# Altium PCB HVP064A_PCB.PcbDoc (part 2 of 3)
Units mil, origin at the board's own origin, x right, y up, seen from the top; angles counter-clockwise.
Board outline 5750 x 4500 mil, 2 copper layers (Top Layer, Bottom Layer), stack 62 mil thick; 174 components, 71 nets, 376 pads, 361 vias.
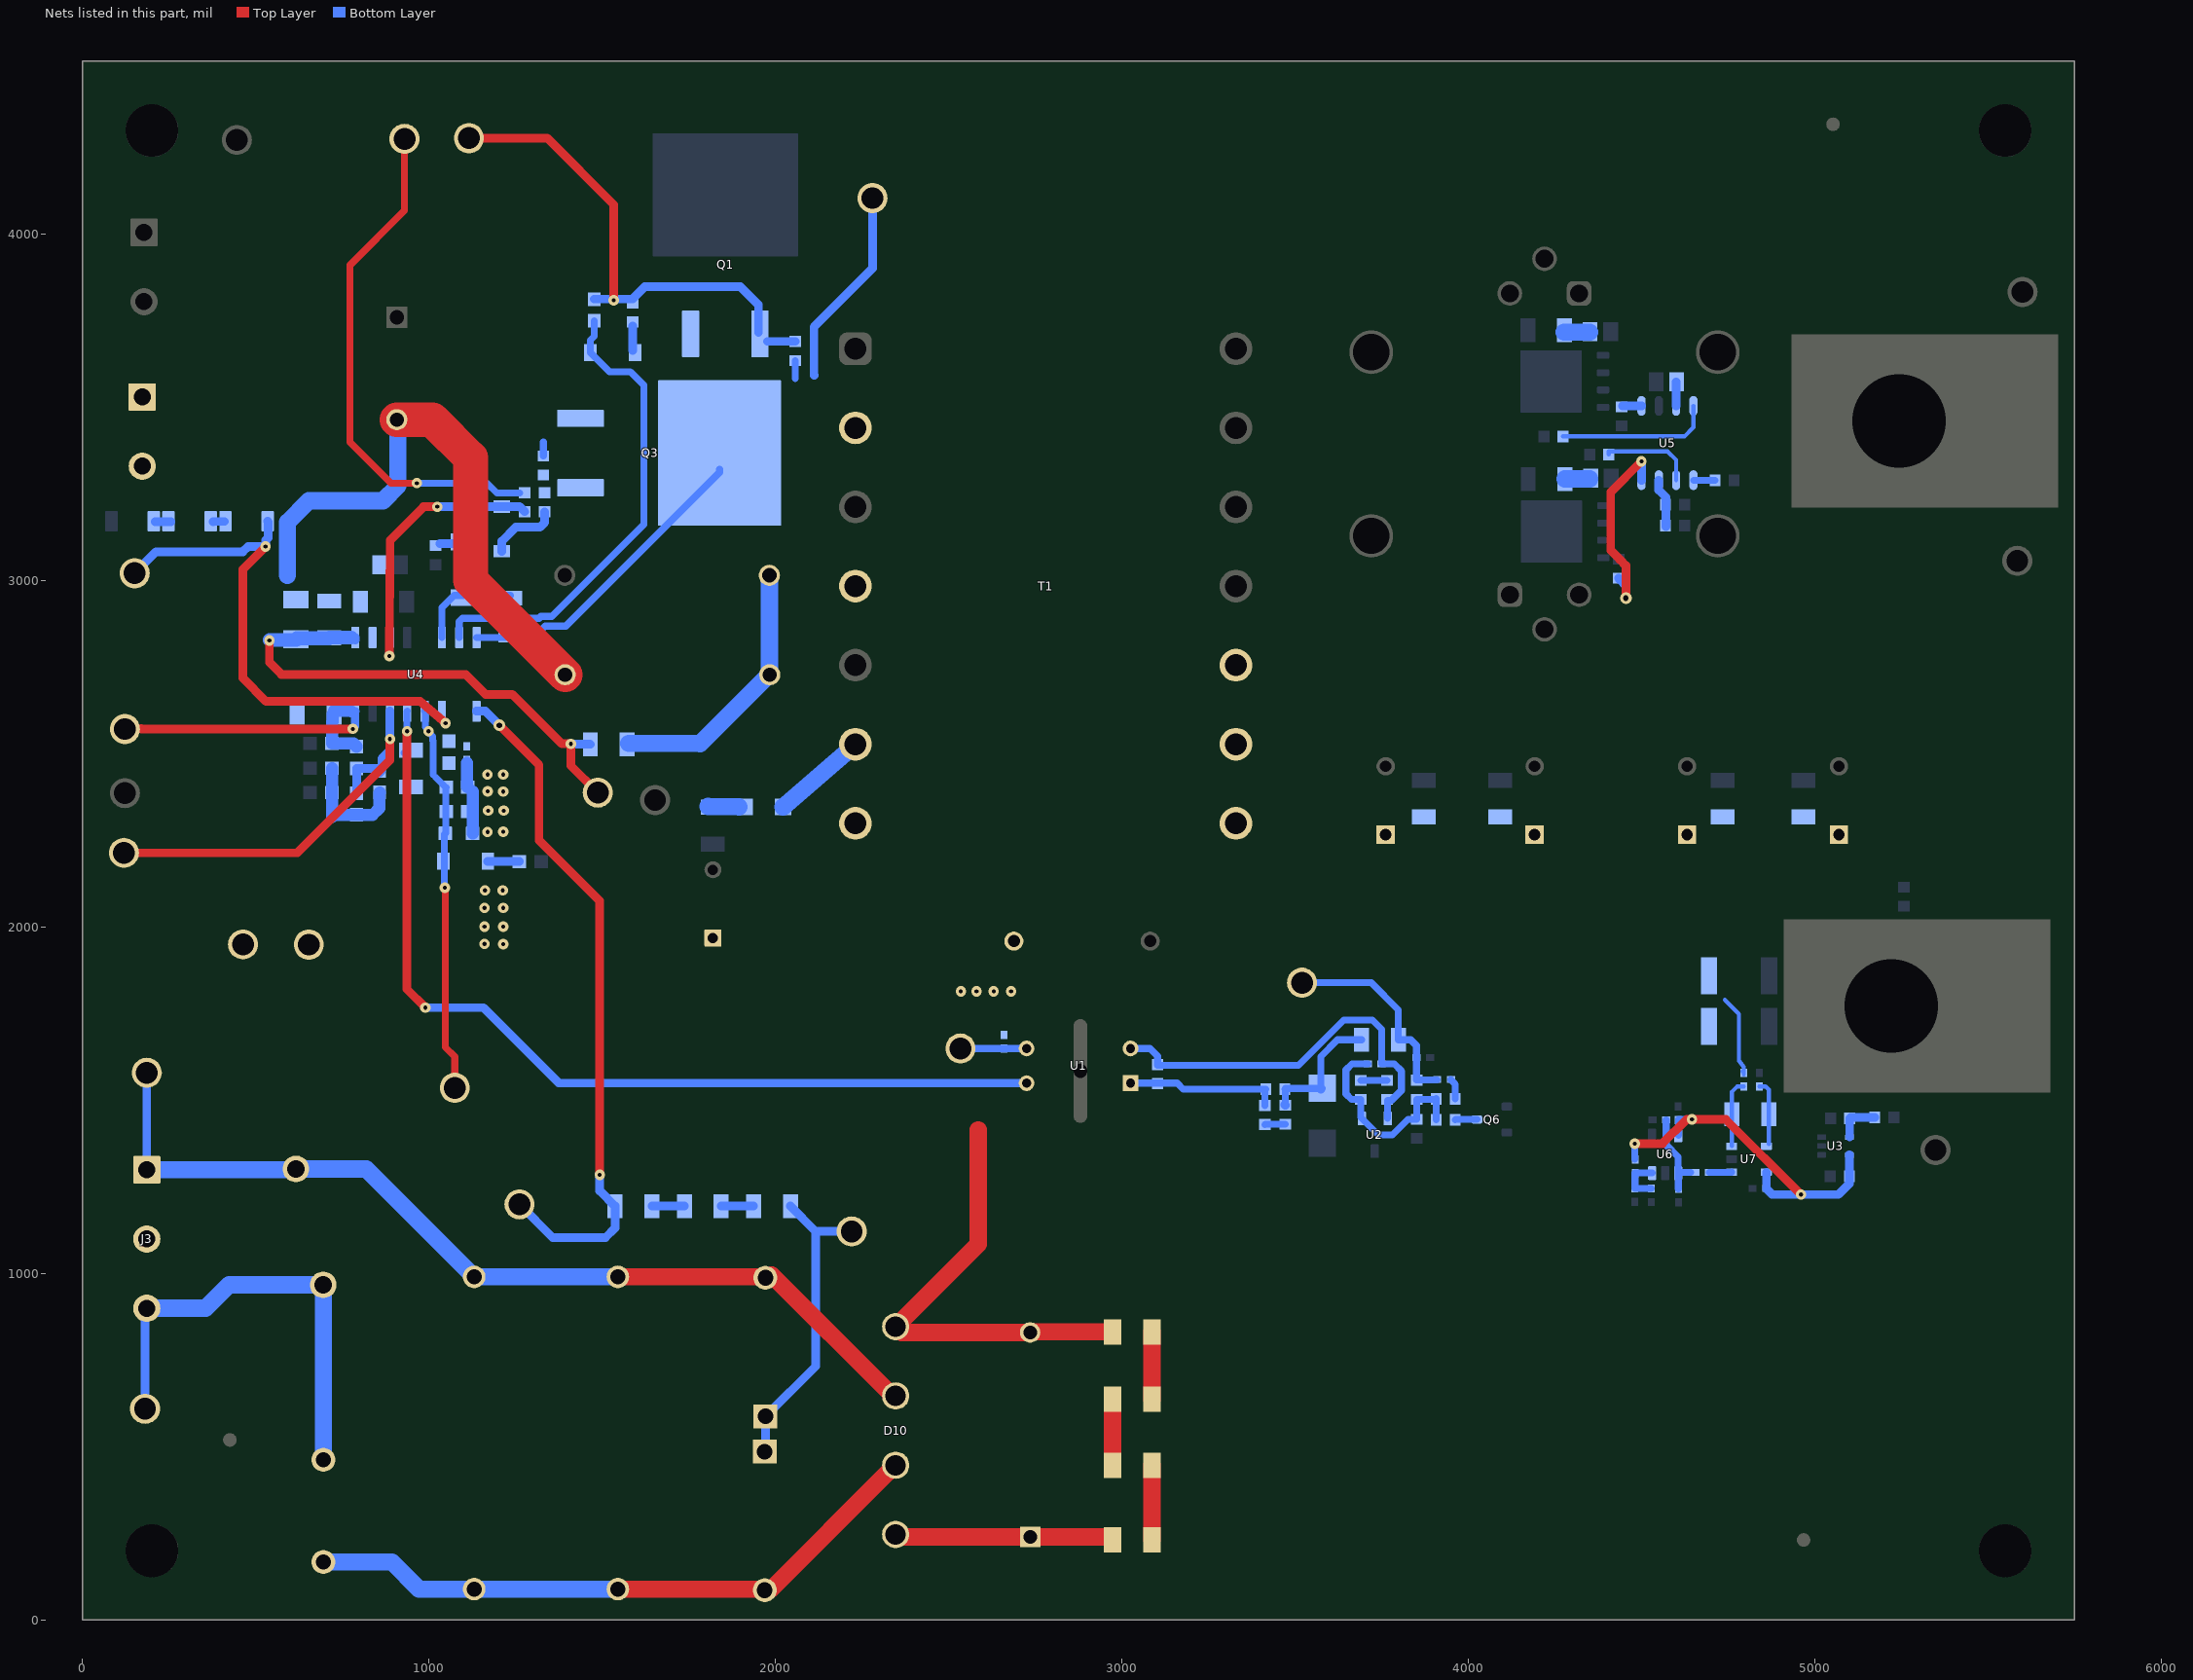
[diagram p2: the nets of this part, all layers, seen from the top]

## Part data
5VP VCC Vin Vout: library part CMP-0055147-2, "Test Point, Multipurpose, Red, TH", Color=Red, Manufacturer="Keystone Electronics", Supplier Part Number 1=36-5010-ND
BLK HG HV HV_diode I_opt ISNS L LG LL N OVP_OTP SW TSET: library part CMP-0055149-2, "Test Point, Multipurpose, White, TH", Color=White, Manufacturer="Keystone Electronics", Supplier Part Number 1=36-5012-ND
C1 C17: library part CMP-0012346-3, "CAP, Film, 0.015 uF, 1250 V, +/- 5%, AEC-Q200 Grade 3, TH", Cap_Case=18x7x12.5, Manufacturer=TDK, Supplier Part Number 1=495-1359-ND, Tolerance_%=5%, Value1=Unknown, Value2=1250V, ValueDisplayed=0.015uF
C2 C19: library part CMP-0008098-2, "CAP, CERM, 1200 pF, 100 V, +/- 5%, C0G/NP0, 0805", Cap_Case=0805, Manufacturer=MuRata, Supplier Part Number 1=GRM2165C2A122JA01D-ND, TempCo=C0G/NP0, Tolerance_%=5%, Value1=Unknown, Value2=100V, ValueDisplayed=1200pF
C3 C4 C8 C9: library part CMP-0010541-2, "CAP, AL, 470 uF, 35 V, +/- 20%, 0.03 ohm, TH", Cap_Case=10x16mm, Manufacturer=Nichicon, Supplier Part Number 1=493-6882-ND, Tolerance_%=20%, Value1="0.03 ohm", Value2=35V, ValueDisplayed=470uF
C5 C6 C10 C11: library part CMP-0008654-2, "CAP, CERM, 22 uF, 25 V, +/- 20%, X5R, 1206_190", Cap_Case=1206, Manufacturer=TDK, Supplier Part Number 1=445-6000-1-ND, TempCo=X5R, Tolerance_%=20%, Value1=Unknown, Value2=25V, ValueDisplayed=22uF
C7: library part CMP-0010043-2, "CAP, AL, 68 uF, 450 V, +/- 20%, TH", Cap_Case=18x31.5mm, Manufacturer=Chemi-Con, Supplier Part Number 1=565-1479-ND, Tolerance_%=20%, Value1=Unknown, Value2=450V, ValueDisplayed=68uF
C12: library part CMP-0006762-4, "CAP, CERM, 100 pF, 50 V, +/- 1%, C0G/NP0, 0603", Cap_Case=0603, Manufacturer=AVX, Supplier Part Number 1=478-6202-1-ND, TempCo=C0G/NP0, Tolerance_%=1%, Value1=Unknown, Value2=50V, ValueDisplayed=100pF
C13: library part CMP-0006976-5, "CAP, CERM, 1000 pF, 50 V, +/- 10%, X7R, 0603", Cap_Case=0603, Manufacturer=Kemet, Supplier Part Number 1=399-5348-1-ND, TempCo=X7R, Tolerance_%=10%, Value1=Unknown, Value2=50V, ValueDisplayed=1000pF
C14: library part CMP-0008885-2, "CAP, CERM, 150 pF, 630 V, +/- 5%, C0G/NP0, 1206", Cap_Case=1206, Manufacturer=MuRata, Supplier Part Number 1=490-5274-1-ND, TempCo=C0G/NP0, Tolerance_%=5%, Value1=Unknown, Value2=630V, ValueDisplayed=150pF
C15 C34: library part CMP-0007883-2, "CAP, CERM, 2.2 uF, 35 V, +/- 10%, X7R, 0805", Cap_Case=0805, Manufacturer=TDK, Supplier Part Number 1=445-14547-1-ND, TempCo=X7R, Tolerance_%=10%, Value1=Unknown, Value2=35V, ValueDisplayed=2.2uF
C16: library part CMP-0098283-1, "Cap Aluminum Lytic 330uF 35V 20% (10 X 16mm) Radial 5mm 1430mA 4000h 105C Bulk", Digikey Part Number=1189-3963-ND, Leakage Current=115.5uA, Manufacturer=Rubycon, Mouser Part Number=232-35ZL330MEFC10X16, Operating Temperature Range="-40°C to +105°C", Tolerance_%=20%, ValueDisplayed=330uF
C18: library part CMP-0081062-1, "CAP, CERM, 10 µF, 25 V,+/- 5%, X7R, AEC-Q200 Grade 1, 1206", Cap_Case=1206_180, Manufacturer=Kemet, Supplier Part Number 1=399-15734-1-ND, TempCo=X7R, Tolerance_%=5%, Value2=25V, ValueDisplayed=10µF
C20: library part CMP-0008462-2, "CAP, CERM, 100 pF, 100 V, +/- 5%, C0G/NP0, 1206", Cap_Case=1206, Manufacturer=AVX, Supplier Part Number 1=478-1444-1-ND, TempCo=C0G/NP0, Tolerance_%=5%, Value1="0.701 ohm", Value2=100V, ValueDisplayed=100pF
C21: library part CMP-0006982-4, "CAP, CERM, 220 pF, 50 V, +/- 10%, X7R, 0603", Cap_Case=0603, Manufacturer=Kemet, Supplier Part Number 1=399-5342-1-ND, TempCo=X7R, Tolerance_%=10%, Value1=Unknown, Value2=50V, ValueDisplayed=220pF
C22: library part CMP-0009595-2, "CAP, CERM, 1000 pF,  V, +/- 20%, E, D7xT6mm", Cap_Case=7x6x11mm, Manufacturer=TDK, Supplier Part Number 1=445-174535-ND, TempCo=E, Tolerance_%=20%, Value1=Unknown, Value2=V, ValueDisplayed=1000pF
C23 C25: library part CMP-0064913-2, "CAP, CERM, 150 pF, 50 V,+/- 5%, C0G/NP0, 0402", Cap_Case=0402, Manufacturer="Wurth Elektronik", Supplier Part Number 1=732-7476-1-ND, TempCo=C0G/NP0, Tolerance_%=5%, Value1=Unknown, Value2=50V, ValueDisplayed=150pF
C24: library part CMP-0120451-1, "C1206 3,000 pF C0G 5.00% 50 V", Digikey Part Number=C1206C302J5GACTU-ND, Manufacturer=KEMET, Mouser Part Number=80-C1206C302J5G, Operating Temperature Range="-55°C to +150°C", TempCo=15%, Temperature Characteristic=C0G, Tolerance_%=0.05%, ValueDisplayed=3nF
C26: library part CMP-0006726-4, "CAP, CERM, 0.01 uF, 100 V, +/- 5%, X7R, 0603", Cap_Case=0603, Manufacturer=AVX, Supplier Part Number 1=478-3700-1-ND, TempCo=X7R, Tolerance_%=5%, Value1="0.098 ohm", Value2=100V, ValueDisplayed=0.01uF
C27 C28: library part CMP-0007120-4, "CAP, CERM, 1 uF, 16 V, +/- 10%, X7R, 0603", Cap_Case=0603, Manufacturer="Taiyo Yuden", Supplier Part Number 1=1683647, TempCo=X7R, Tolerance_%=10%, Value1=Unknown, Value2=16V, ValueDisplayed=1uF
C29: library part CMP-0064950-2, "CAP, CERM, 0.1 uF, 25 V,+/- 5%, C0G/NP0, 1206", Cap_Case=1206, Manufacturer=MuRata, Supplier Part Number 1=490-1767-1-ND, TempCo=C0G/NP0, Tolerance_%=5%, Value1=Unknown, Value2=25V, ValueDisplayed=0.1uF
C30: library part CMP-0008693-2, "CAP, CERM, 4.7 uF, 25 V, +/- 10%, X7R, 1206", Cap_Case=1206, Manufacturer=TDK, Supplier Part Number 1=445-14797-1-ND, TempCo=X7R, Tolerance_%=10%, Value1=Unknown, Value2=25V, ValueDisplayed=4.7uF
C31: library part CMP-0006983-4, "CAP, CERM, 2200 pF, 50 V, +/- 10%, X7R, 0603", Cap_Case=0603, Manufacturer=Kemet, Supplier Part Number 1=399-5341-1-ND, TempCo=X7R, Tolerance_%=10%, Value1=Unknown, Value2=50V, ValueDisplayed=2200pF
C32: library part CMP-0006236-2, "CAP, CERM, 0.01 uF, 50 V, +/- 5%, X7R, 0402", Cap_Case=0402, Manufacturer=Kemet, Supplier Part Number 1=399-7758-1-ND, TempCo=X7R, Tolerance_%=5%, Value1=Unknown, Value2=50V, ValueDisplayed=0.01uF
C35: library part CMP-0007380-4, "CAP, CERM, 1 uF, 16 V, +/- 10%, X7R, 0603", Cap_Case=0603, Manufacturer=MuRata, Supplier Part Number 1=490-10734-1-ND, TempCo=X7R, Tolerance_%=10%, Value1=Unknown, Value2=16V, ValueDisplayed=1uF
C37: library part CMP-0006591-2, "CAP, CERM, 0.1 uF, 16 V, +/- 10%, X5R, 0402", Cap_Case=0402, Manufacturer=MuRata, Supplier Part Number 1=490-5415-1-ND, TempCo=X5R, Tolerance_%=10%, Value1=Unknown, Value2=16V, ValueDisplayed=0.1uF
C38: library part CMP-0008568-2, "CAP, CERM, 47 pF, 500 V, +/- 5%, C0G/NP0, 1206", Cap_Case=1206, Manufacturer=AVX, Supplier Part Number 1=12067A470JAT2A-ND, TempCo=C0G/NP0, Tolerance_%=5%, Value1=Unknown, Value2=500V, ValueDisplayed=47pF
C39: library part CMP-0012412-3, "CAP, Film, 0.47 uF, 630 V, +/- 10%, TH", Manufacturer=TDK, Supplier Part Number 1=495-6910-ND, Tolerance_%=10%, Value1=Unknown, Value2=630V, ValueDisplayed=0.47uF
C40 C41: library part CMP-0074805-2, "CAP, Film, 1 µF, X2 275 VAC, +/- 20%, TH", Cap_Case=26.5x10x18.5mm, Manufacturer=Kemet, Supplier Part Number 1=399-6795-ND, Tolerance_%=20%, Value2=560V, ValueDisplayed=1µF
C42 C43: library part CMP-0006410-2, "CAP, CERM, 100 pF, 50 V, +/- 5%, C0G/NP0, 0402", Cap_Case=0402, Manufacturer=MuRata, Supplier Part Number 1=81-GRM1555C1H101JA1D, TempCo=C0G/NP0, Tolerance_%=5%, Value1=Unknown, Value2=50V, ValueDisplayed=100pF
C44: library part CMP-0006607-2, "CAP, CERM, 0.1 uF, 25 V, +/- 10%, X5R, 0402", Cap_Case=0402, Manufacturer=MuRata, Supplier Part Number 1=490-5920-1-ND, TempCo=X5R, Tolerance_%=10%, Value1=Unknown, Value2=25V, ValueDisplayed=0.1uF
C46: library part CMP-0006941-4, "CAP, CERM, 4700 pF, 100 V, +/- 5%, C0G/NP0, 0603", Cap_Case=0603, Manufacturer=Kemet, Supplier Part Number 1=399-9974-1-ND, TempCo=C0G/NP0, Tolerance_%=5%, Value1=Unknown, Value2=100V, ValueDisplayed=4700pF
D1 D4: library part CMP-0029001-2, "Diode, Ultrafast, 100 V, 0.15 A, SOD-123", Manufacturer="Diodes Inc.", Value1=0.15A, Value2=1.25V
D2 D5: library part CMP-0028866-3, "Diode, Schottky, 100 V, 20 A, AEC-Q101, TH", Manufacturer=STMicroelectronics, Value1=20A, Value2=0.8V
D3: library part CMP-0028977-2, "Diode, Schottky, 100 V, 2 A, AEC-Q101, SOD-123W", Manufacturer=Nexperia, Value1=2A, Value2=0.83V
D6: library part CMP-0005522-4, "Diode, Zener, 11 V, 1.5 W, SMA", Manufacturer="ON Semiconductor", Power_W=1.5W
D7: library part CMP-0029162-2, "Diode, Ultrafast, 600 V, 1 A, AEC-Q101, SMAF", Manufacturer="Fairchild Semiconductor", Value1=1A, Value2=1.7V
D8 D9: library part CMP-0029188-2, "Diode, P-N, 1000 V, 1 A, TH", Manufacturer=Vishay-Semiconductor, Value1=1A, Value2=1.1V
D10: library part CMP-0029222-3, "Diode, Switching-Bridge, 420 V, 8 A, TH", Manufacturer="Micro Commercial Components", Value1=8A, Value2=1V
D11: library part CMP-0085135-1, "Diode, Zener, 15 V, 500 mW, SOD-123", Manufacturer="Diodes Inc.", Power_W=500mW, Value1=0.5W
FID1 FID2 FID3: library part CMP-0077181-1, "Fiducial mark.  There is nothing to buy or mount.", Manufacturer=N/A
H1 H2 H3 H4: library part CMP-0003690-1, Manufacturer=Keystone, Supplier Part Number 1=36-4824-ND
H5 H6 H7 H8: library part CMP-0003679-1, Manufacturer=Keystone, Supplier Part Number 1=36-1903C-ND
H9 H10: library part CMP-0004053-1, Manufacturer=Aavid, Supplier Part Number 1=HS382-ND
Inj: library part CMP-0055150-2, "Test Point, Multipurpose, Orange, TH", Color=Orange, Manufacturer="Keystone Electronics", Supplier Part Number 1=36-5013-ND
J1 J2: library part CMP-0074910-1, "Terminal Block, 5.08 mm, 2x1, Brass, TH", Color=Blue, Current_A=15A, Manufacturer="On-Shore Technology", Supplier Part Number 1=ED1609-ND, Voltage_V=300V
J3: library part CMP-0074911-1, "Terminal Block, 5.08 mm, 3x1, Brass, TH", Color=Blue, Current_A=15A, Manufacturer="On-Shore Technology", Supplier Part Number 1=ED1610-ND, Voltage_V=300V
Logo1: library part CMP-0074835-1, "IEC 61010-1 High Voltage Warning"
LOGO2: library part CMP-0074836-1, "IEC 61010-1 Caution Warning"
LOGO3: library part CMP-0074837-2, "IEC 61010-1 Hot Surface Warning", Manufacturer="Texas Instruments"
Logo4: library part CMP-0074844-1
Logo5: library part CMP-0074838-1, "Texas Instrument Corporate Signature"
Logo6: library part CMP-0074847-1, "FCC_disclaimer"
Logo7: library part CMP-0074769-3, Manufacturer="Texas Instruments"
Q1 Q3: library part CMP-0065576-1, "Power Transistor MOSFET N-Channel Enhancement 600V 21A 3-Pin D2PAK T/R", Digikey Part Number=448-IPB60R105CFD7ATMA1CT-ND, Drain To Source Breakdown Voltage=600V, Input Capacitace At Vds="1752pF @ 400V", Manufacturer=Infineon, Mouser Part Number=726-IPB60R105CFD7ATM, Operating Temperature Range="-55°C to +150°C", Power_W=106W, Pulse Drain Current=79A, Typ Forward Diode Voltage=1V
Q2 Q4: library part CMP-0000711-1, "MOSFET, N-CH, 40 V, 100 A, DQJ0008A (VSONP-8)", Alternate Manufacturer=None, Manufacturer="Texas Instruments", Supplier Part Number 1=CSD18511Q5A-ND, Value1=0.003, Value2="63 nC"
Q6: library part CMP-0000773-1, "MOSFET, N-CH, 60 V, 0.3 A, SOT-23", Alternate Manufacturer=None, Manufacturer=Vishay-Siliconix, Supplier Part Number 1=2N7002K-T1-E3CT-ND, Value2="0.4 nC"
R1 R6: library part CMP-0023107-5, "RES, 42.2, 1%, 0.1 W, 0603", Manufacturer=Yageo, Power_W=100mW, Supplier Part Number 1=311-42.2HRCT-ND, TempCo="100 ppm/C", Tolerance_%=1%, Value2=0.1W, Value_Code=42R2, ValueDisplayed=42.2
R2 R7: library part CMP-0017851-2, "RES, 10.0, 1%, 0.25 W, 1206", Manufacturer="Yageo America", Power_W=250mW, Supplier Part Number 1=311-10.0FRCT-ND, TempCo="200 ppm/C", Tolerance_%=1%, Value2=0.25W, Value_Code=10R0, ValueDisplayed=10.0
R3 R8: library part CMP-0022900-4, "RES, 1.00, 1%, 0.1 W, 0603", Manufacturer=Yageo, Power_W=100mW, Supplier Part Number 1=311-1.00HRCT-ND, TempCo="200 ppm/C", Tolerance_%=1%, Value2=0.1W, Value_Code=1R00, ValueDisplayed=1.00
R4 R11: library part CMP-0023167-5, "RES, 51.0 k, 1%, 0.1 W, 0603", Manufacturer=Yageo, Power_W=100mW, Supplier Part Number 1=311-51.0KHRCT-ND, TempCo="100 ppm/C", Tolerance_%=1%, Value2=0.1W, Value_Code=51k0, ValueDisplayed=51.0k
R5: library part CMP-0018748-3, "RES, 0, 5%, 0.25 W, AEC-Q200 Grade 0, 1206", Manufacturer=Panasonic, Power_W=250mW, Supplier Part Number 1=P0.0ECT-ND, TempCo="600 ppm/C", Tolerance_%=5%, Value2=0.25W, Value_Code=0000, ValueDisplayed=0
R9 R12: library part CMP-0016512-2, "RES, 0.005, 1%, 1.5 W, 2010", Manufacturer="Stackpole Electronics Inc", Power_W=1.5W, Supplier Part Number 1=CSNL2010FT5L00CT-ND, TempCo="50 ppm/C", Tolerance_%=1%, Value_Code=5L000, ValueDisplayed=0.005
R14: library part CMP-0022899-4, "RES, 1.00 M, 1%, 0.1 W, 0603", Manufacturer=Yageo, Power_W=100mW, Supplier Part Number 1=311-1.00MHRCT-ND, TempCo="100 ppm/C", Tolerance_%=1%, Value2=0.1W, Value_Code=1M00, ValueDisplayed=1.00M
R15: library part CMP-0027004-2, "RES, 0, 5%, 0.063 W, 0402", Manufacturer="Yageo America", Power_W=63mW, Supplier Part Number 1=311-0.0JRCT-ND, TempCo="200 ppm/C", Tolerance_%=5%, Value2=0.063W, Value_Code=0000, ValueDisplayed=0
R16: library part CMP-0022981-5, "RES, 2.05 k, 1%, 0.1 W, 0603", Manufacturer=Yageo, Power_W=100mW, Supplier Part Number 1=311-2.05KHRCT-ND, TempCo="100 ppm/C", Tolerance_%=1%, Value2=0.1W, Value_Code=2k05, ValueDisplayed=2.05k
R17: library part CMP-0086176-1, "RES, 0, 0.75 W, AEC-Q200 Grade 0, 1206", Manufacturer=Vishay-Dale, Power_W=750mW, Tolerance_%=0%, Value2=0.75W, Value_Code=0
R18: library part CMP-0023332-5, "RES, 9.09 k, 1%, 0.1 W, 0603", Manufacturer=Yageo, Power_W=100mW, Supplier Part Number 1=311-9.09KHRCT-ND, TempCo="100 ppm/C", Tolerance_%=1%, Value2=0.1W, Value_Code=9k09, ValueDisplayed=9.09k
R19: library part CMP-0022800-4, "RES, 147 k, 1%, 0.1 W, 0603", Manufacturer=Yageo, Power_W=100mW, Supplier Part Number 1=311-147KHRCT-ND, TempCo="100 ppm/C", Tolerance_%=1%, Value2=0.1W, Value_Code=147k
R20: library part CMP-0022684-3, "RES, 10.0 k, 1%, 0.1 W, 0603", Manufacturer=Panasonic, Power_W=100mW, Supplier Part Number 1=P10.0KHCT-ND, TempCo="100 ppm/C", Tolerance_%=1%, Value2=0.1W, Value_Code=10k0, ValueDisplayed=10.0k
R21: library part CMP-0026658-1, "RES, 10.0 k, 1%, 0.1 W, 0402", Manufacturer=Panasonic, Power_W=100mW, Supplier Part Number 1=P10.0KLCT-ND, TempCo="100 ppm/C", Tolerance_%=1%, Value2=0.1W, Value_Code=10k0, ValueDisplayed=10.0k
R22: library part CMP-0023036-5, "RES, 33.2 k, 1%, 0.1 W, 0603", Manufacturer=Yageo, Power_W=100mW, Supplier Part Number 1=311-33.2KHRCT-ND, TempCo="100 ppm/C", Tolerance_%=1%, Value2=0.1W, Value_Code=33k2, ValueDisplayed=33.2k
R23: library part CMP-0022830-5, "RES, 16.9 k, 1%, 0.1 W, 0603", Manufacturer=Yageo, Power_W=100mW, Supplier Part Number 1=311-16.9KHRCT-ND, TempCo="100 ppm/C", Tolerance_%=1%, Value2=0.1W, Value_Code=16k9, ValueDisplayed=16.9k
R24 R31 R32: library part CMP-0025885-5, "RES, 0, 5%, 0.1 W, 0603", Manufacturer=Yageo, Power_W=100mW, Supplier Part Number 1=311-0.0GRCT-ND, TempCo="200 ppm/C", Tolerance_%=5%, Value2=0.1W, Value_Code=0000, ValueDisplayed=0
R25: library part CMP-0022711-2, "RES, 2.20, 1%, 0.1 W, 0603", Manufacturer=Panasonic, Power_W=100mW, Supplier Part Number 1=P2.2AJCT-ND, TempCo="200 ppm/C", Tolerance_%=1%, Value2=0.1W, Value_Code=2R20, ValueDisplayed=2.20
R26 R27 R28: library part CMP-0016708-3, "RES, 1.65 k, 1%, 0.25 W, AEC-Q200 Grade 0, 1206", Manufacturer=Vishay-Dale, Power_W=250mW, Supplier Part Number 1=541-1.65KFCT-ND, TempCo="100 ppm/C", Tolerance_%=1%, Value2=0.25W, Value_Code=1k65, ValueDisplayed=1.65k
R29 R30 R34: library part CMP-0087456-2, "3.3 MOhms ±1% 0.25W, 1/4W Chip Resistor 1206 (3216 Metric) Automotive AEC-Q200, High Voltage Thick Film", Manufacturer="Rohm Semiconductor", Power_W=250mW, TempCo=100ppm/°C, Tolerance_%=1%
R33: library part CMP-0023178-4, "RES, 549 k, 1%, 0.1 W, 0603", Manufacturer=Yageo, Power_W=100mW, Supplier Part Number 1=311-549KHRCT-ND, TempCo="100 ppm/C", Tolerance_%=1%, Value2=0.1W, Value_Code=549k
R35: library part CMP-0022751-4, "RES, 10.0, 1%, 0.1 W, 0603", Manufacturer=Yageo, Power_W=100mW, Supplier Part Number 1=311-10.0HRCT-ND, TempCo="100 ppm/C", Tolerance_%=1%, Value2=0.1W, Value_Code=10R0, ValueDisplayed=10.0
R36: library part CMP-0022796-4, "RES, 140 k, 1%, 0.1 W, 0603", Manufacturer=Yageo, Power_W=100mW, Supplier Part Number 1=311-140KHRCT-ND, TempCo="100 ppm/C", Tolerance_%=1%, Value2=0.1W, Value_Code=140k
R37: library part CMP-0024147-3, "RES, 35.7 k, 0.1%, 0.1 W, 0603", Manufacturer="Yageo America", Power_W=100mW, TempCo="25 ppm/C", Tolerance_%=0.1%, Value2=0.1W, Value_Code=35k7, ValueDisplayed=35.7k
R38: library part CMP-0023846-3, "RES, 191 k, 0.1%, 0.1 W, 0603", Manufacturer="Yageo America", Power_W=100mW, TempCo="25 ppm/C", Tolerance_%=0.1%, Value2=0.1W, Value_Code=191k
R39 R40 R45 R49: library part CMP-0018577-3, "RES, 10 M, 5%, 0.25 W, AEC-Q200 Grade 0, 1206", Manufacturer=Vishay-Dale, Power_W=250mW, Supplier Part Number 1=541-10MECT-ND, TempCo="200 ppm/C", Tolerance_%=5%, Value2=0.25W, Value_Code=10M0, ValueDisplayed=10M
R41 R42: library part CMP-0026432-2, "RES, 4.75, 1%, 0.063 W, AEC-Q200 Grade 0, 0402", Manufacturer=Vishay-Dale, Power_W=63mW, Supplier Part Number 1=541-4.75LLCT-ND, TempCo="100 ppm/C", Tolerance_%=1%, Value2=0.063W, Value_Code=4R75, ValueDisplayed=4.75
R43 R47: library part CMP-0023441-3, "RES, 15.0 k, 0.1%, 0.1 W, 0603", Manufacturer="Susumu Co Ltd", Power_W=100mW, Supplier Part Number 1=RG16P15.0KBCT-ND, TempCo="25 ppm/C", Tolerance_%=0.1%, Value2=0.1W, Value_Code=15k0, ValueDisplayed=15.0k
R44: library part CMP-0026659-2, "RES, 100 k, 1%, 0.1 W, 0402", Manufacturer=Panasonic, Power_W=100mW, TempCo="100 ppm/C", Tolerance_%=1%, Value2=0.1W, Value_Code=100k
R46: library part CMP-0096703-1, "NTC Thermistor 470k 0603 (1608 Metric)", B Tolerance=3%, Digikey Part Number=495-B57371V2474J060CT-ND, Manufacturer=TDK, Mouser Part Number=871-B57371V2474J060, Operating Temperature Range="-55°C to +125°C", Power_W=180mW, Tolerance_%=5%
R48: library part CMP-0026463-2, "RES, 5.11 k, 1%, 0.063 W, AEC-Q200 Grade 0, 0402", Manufacturer=Vishay-Dale, Power_W=63mW, Supplier Part Number 1=541-5.11KLCT-ND, TempCo="100 ppm/C", Tolerance_%=1%, Value2=0.063W, Value_Code=5k11, ValueDisplayed=5.11k
R50: library part CMP-0026329-2, "RES, 3.01 k, 1%, 0.063 W, AEC-Q200 Grade 0, 0402", Manufacturer=Vishay-Dale, Power_W=63mW, Supplier Part Number 1=541-3.01KLCT-ND, TempCo="100 ppm/C", Tolerance_%=1%, Value2=0.063W, Value_Code=3k01, ValueDisplayed=3.01k
R51: library part CMP-0018063-2, "RES, 205, 1%, 0.25 W, 1206", Manufacturer="Yageo America", Power_W=250mW, Supplier Part Number 1=311-205FRCT-ND, TempCo="100 ppm/C", Tolerance_%=1%, Value2=0.25W, Value_Code=205R, ValueDisplayed=205
R52: library part CMP-0026203-2, "RES, 261 k, 1%, 0.063 W, AEC-Q200 Grade 0, 0402", Manufacturer=Vishay-Dale, Power_W=63mW, Supplier Part Number 1=541-261KLCT-ND, TempCo="100 ppm/C", Tolerance_%=1%, Value2=0.063W, Value_Code=261k
R53 R54: library part CMP-0024324-2, "RES, 536, 0.1%, 0.1 W, 0603", Manufacturer="Yageo America", Power_W=100mW, TempCo="25 ppm/C", Tolerance_%=0.1%, Value2=0.1W, Value_Code=536R, ValueDisplayed=536
R55: library part CMP-0023074-4, "RES, 39.2, 1%, 0.1 W, 0603", Manufacturer=Yageo, Power_W=100mW, Supplier Part Number 1=311-39.2HRCT-ND, TempCo="100 ppm/C", Tolerance_%=1%, Value2=0.1W, Value_Code=39R2, ValueDisplayed=39.2
R56: library part CMP-0023285-5, "RES, 80.6 k, 1%, 0.1 W, 0603", Manufacturer=Yageo, Power_W=100mW, Supplier Part Number 1=311-80.6KHRCT-ND, TempCo="100 ppm/C", Tolerance_%=1%, Value2=0.1W, Value_Code=80k6, ValueDisplayed=80.6k
R57: library part CMP-0022871-5, "RES, 1.21 k, 1%, 0.1 W, 0603", Manufacturer=Yageo, Power_W=100mW, Supplier Part Number 1=311-1.21KHRCT-ND, TempCo="100 ppm/C", Tolerance_%=1%, Value2=0.1W, Value_Code=1k21, ValueDisplayed=1.21k
RT1: library part CMP-0002554-2, "Thermistor NTC, 4.70 ohm, 20%, 15x7mm", Manufacturer=TDK, Power_W=3.1W, Supplier Part Number 1=495-2099-ND, Tolerance_%=20%
RV1: library part CMP-0080568-2, "VARISTOR 1200V 10KA DISC 20MM", Manufacturer=Littelfuse
SGND1 SGND2 TP8 TP9: library part CMP-0055148-2, "Test Point, Multipurpose, Black, TH", Color=Black, Manufacturer="Keystone Electronics", Supplier Part Number 1=36-5011-ND
T1: library part CMP-0065589-1, "TRANSFORMER-", Frequency_Fixed=60-130kHz, Manufacturer="Wurth Electronics", Operating Temperature Range="-40°C to +125°C", Voltage_Isolation_Vrms=3kV
T2 T3: library part CMP-0075010-2, "Terminal 70A Lug", Manufacturer=Panduit, Supplier Part Number 1=CXS70-14-C-ND
U1: library part CMP-0083653-1, "Optocoupler, 5.3 kV, 100-200% CTR, SMT", Manufacturer=Vishay-Semiconductor, Supplier Part Number 1=VO618A-3-ND, Voltage_Isolation_Vrms=5.3kV
U2: library part CMP-0033066-1, "Low-Voltage Adjustable Precision Shunt Regulator, 129 ppm / degC, 80 mA, 0 to 70 degC, 3-pin SOT-23 (DBZ), Green (RoHS & no Sb/Br)", Manufacturer="Texas Instruments", Rating=Catalog, Temp Coeff(Max)(ppm/ degree C)=129
U3: library part CMP-0035742-2, "Single Output LDO, 50 mA, Fixed 5 V Output, 3 to 24 V Input, 5-pin SC70 (DCK), -40 to 85 degC, Green (RoHS & no Sb/Br)", Manufacturer="Texas Instruments"
U4: library part CMP-0095297-2, "750kHz Wide VIN/VOUT Range LLC Controller Optimized for Light Load Efficiency", Manufacturer="Texas Instruments", Max Supply Voltage=18.5V, Operating Temperature Range="-40°C to +150°C", Switching Frequency=30-750kHz
U5: library part CMP-0079610-1, "High Performance Synchronous Rectifier Driver for LLC Resonant Converter, D0008A (SOIC-8)", Alternate Manufacturer="Texas Instruments"
U6: library part CMP-0068476-2, "Single General Purpose, Low Voltage, Tiny Pack Comparator, 5-pin SOT-23, Pb-Free", Manufacturer="Texas Instruments", Package Reference=DBV0005A, PackageTopMarking=C12*XTT, PowerWise=Y
U7: library part CMP-0013052-2, "Low- and High-Side Measurement, Multichannel, Voltage Output, Current-Sense Amplifier, DBV0005A (SOT-5)", Alternate Manufacturer="Texas Instruments"
ZZ1: library part CMP-0077236-1
ZZ2: library part CMP-0077237-1
ZZ3: library part CMP-0077238-1

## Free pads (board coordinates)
  oval 40x300 hole 40 slot 300 at 90 deg unplated mask+5: 3(2880,1585.08)

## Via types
v1: diameter 30, hole 12, Top Layer to Bottom Layer, 243 vias
v2: diameter 32, hole 16, Top Layer to Bottom Layer, 116 vias
v3: diameter 34, hole 16, Top Layer to Bottom Layer, 2 vias

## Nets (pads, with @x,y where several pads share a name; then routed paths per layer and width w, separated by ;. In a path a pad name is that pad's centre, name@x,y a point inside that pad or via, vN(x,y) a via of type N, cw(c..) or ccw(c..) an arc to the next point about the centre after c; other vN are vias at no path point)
5V: C28.1 C37.1 C44.1 R44.2 U3.5 U6.5 U7.5 | length 1116.5
  Top Layer w25: v1(4480.39,1375.33) 4560.39,1375.33 4630.39,1445.33 v1(4645.39,1445.33) 4743.39,1445.33 v1(4960.39,1228.33)
  Bottom Layer w20: R44.2@4480.39,1331.01 v1(4480.39,1375.33) ; U6.5@4607.07,1399.75 4607.07,1445.33 v1(4645.39,1445.33)
  Bottom Layer w25: U7.5@4860.59,1292.93 4860.59,1244.82 4877.07,1228.33 v1(4960.39,1228.33) 5068.39,1228.33 5099.95,1259.89 C28.1@5099.95,1281.33 ; C28.1@5100.74,1282.12 U3.5@5100.74,1342.74
5VP: 5VP.1 C30.1 R14.2 R33.2 U4.8 | length 884.1
  Top Layer w25: 168.66,2573.87 170.02,2572.52 v1(780.03,2572.52)
  Bottom Layer w20: U4.8@785.19,2621.62 U4.8@786.31,2622.74 ; U4.8@787,2623.43 U4.8@787,2623.7
  Bottom Layer w25: v1(780.03,2572.52) 780.03,2573.87 786.31,2580.16 786.31,2622.74 U4.8@787,2623.43
  Bottom Layer w35: C30.1@725.57,2619.54 721.41,2615.39 721.41,2594.28 719.66,2592.53 R14.2@719.66,2530.47 782.38,2530.47 790.75,2522.1 R33.2@790.75,2521.12 ; C30.1@725.75,2625.29 U4.8@775.19,2623.7
BLK: BLK.1 C32.1 R34.1 R37.2 U4.3 | length 1530.2
  Top Layer w25: v1(528,3099) 462.74,3033.74 462.74,2718.95 529.48,2652.2 973.69,2652.2 v1(1047.88,2588.9)
  Bottom Layer w25: BLK.1@150,3022 212.05,3084.05 462.25,3084.05 477.2,3099 v1(528,3099) 528.96,3099.96 528.96,3117.49 535.99,3124.53 535.99,3170.03 R34.1@534.02,3172
EARTH: J3.2
FB: C24.1 U1.4 U4.5 | length 2770.1
  Top Layer w25: v1(936.28,2565.91) 935.83,2565.47 935.83,1821.52 v1(989.36,1767.99)
  Bottom Layer w20: C24.1@927.66,2503.66 935.39,2511.39 935.39,2622.09 U4.5@937,2623.7
  Bottom Layer w25: v1(989.36,1767.99) 1156.66,1767.99 1374.65,1550 U1.4@2725,1550
HO: D1.1 R1.1 U4.15 | length 1387.3
  Bottom Layer w20: U4.15@1087,2836.3 1087,2883 1096,2892 1317.59,2892 1322.98,2897.39 1354.39,2897.39 1620,3163 1620,3565 1581.26,3603.74 1520.79,3603.74 D1.1@1465.53,3659 1465.53,3694.53 1477,3706 R1.1@1477,3750.5
HS: C29.2 Q1.3 Q3.4 R4.1 SW.1 T1.2 U4.16 | length 1545.1
  Bottom Layer w20: U4.16@1137,2836.3 1235,2836.3 1301.31,2836.3 1334.52,2869.51 1394.51,2869.51 1838.51,3313.51 Q3.4@1838.51,3322.51 ; 2057.36,3583.64 R4.1@2057.36,3636.17
  Bottom Layer w25: C29.2@1233,2834.3 C29.2@1235,2836.3 ; 2112,3593.87 2111.04,3594.82 2111.04,3733.48 2280,3902.43 SW.1@2280,4105
IN+: C3.1 C4.1 C5.2 C6.2 C8.1 C9.1 C10.1 C11.1 R9.1 R12.1 R42.2 T1.8 T1.9 T1.10 | length 245.1
  Top Layer w25: C9.1@4631.61,2267.83 C9.1@4634,2270.22
  Bottom Layer w12: 4740.61,1790.33 4781.39,1749.55 4781.39,1614.16 4795.39,1595.76 R42.2@4795.39,1575.62 ; R42.2@4791.55,1583.86 R42.2@4795.39,1580.01
ISNS: C14.2 C20.1 ISNS.1 R51.2 U4.9 | length 1508
  Top Layer w25: v1(538.94,2828.12) 538.94,2764.81 573.76,2730 1105.49,2730 1162.99,2672.5 1240.07,2672.5 1381.57,2531 1383,2531 1383.53,2530.47 1408.44,2530.47 v1(1409.4,2529.51) 1409.4,2466.39 ISNS.1@1487.09,2388.7
  Bottom Layer w25: v1@537.99,2829.08 v1(538.94,2828.12) v1@539.9,2829.08 ; U4.9@786.31,2829.08 787,2829.76 U4.9@787,2836.3 ; v1(1409.4,2529.51) 1410.15,2528.76 1464.68,2528.76 C14.2@1465.43,2528
  Bottom Layer w40: v1@539.9,2829.08 R51.2@616,2829.08 ; R51.2@616,2831.53 618.63,2834.16 710.69,2834.16 C20.1@712,2835.46 U4.9@775.19,2836.3
LL: C13.1 LL.1 R33.1 R36.2 U4.6 | length 1272.1
  Top Layer w25: LL.1@119.24,2214.76 619.21,2214.76 887,2482.55 v1(887,2543.26)
  Bottom Layer w25: R36.2@790.75,2387.26 R33.1@790.75,2458.12 846.47,2458.12 857.34,2447.25 857.34,2446.26 863.54,2452.46 863.54,2487.32 887,2510.78 v1(887,2543.26) U4.6@887,2623.7
LO: D4.1 R6.1 U4.11 | length 826.1
  Top Layer w25: v1@885.42,2783.96 v1(885.42,2782.94) 887.26,3117.26 984,3214 v1(1024,3214)
  Bottom Layer w20: v1@885.42,2780.23 v1(885.42,2782.94) ; U4.11@887,2836.3 887.14,2782.94 v1@887.14,2782.85
  Bottom Layer w25: v1(1024,3214) D4.1@1209.53,3214 ; D4.1@1210,3214.47 1260.97,3214.47 R6.1@1276,3199.44
NetC1_2: C1.2 C14.1 C17.1 T1.4 | length 774.4
  Bottom Layer w50: C14.1@1576.65,2531 1782.36,2530.09 1982.28,2730 C1.2@1982.28,3016
NetC2_1: C2.1 R2.1 | length 71.3
  Bottom Layer w50: R2.1@4279.15,3294 C2.1@4350.47,3294
NetC19_1: C19.1 R7.1 | length 73.3
  Bottom Layer w50: R7.1@4277.15,3718 C19.1@4350.47,3718
NetC23_1: C23.1 Inj.1 R15.1 R17.2 R19.2 | length 614.8
  Bottom Layer w20: Inj.1@3520,1840 3720,1840 3798.15,1761.85 R17.2@3798.15,1675 3833.64,1675 3850.31,1658.32 R15.1@3850.31,1624 3850.31,1559.24 C23.1@3909.56,1559.24
NetC23_2: C23.2 R20.2 | length 60.3
  Bottom Layer w20: C23.2@3949.69,1560 3962.56,1547.13 R20.2@3962.56,1505
NetC25_1: C25.1 R19.1 R20.1 R22.1 R23.2 R56.1 U2.1 | length 612.2
  Bottom Layer w20: U2.1@3690,1450.53 R22.1@3690,1503.13 3662.87,1503.13 3646.9,1519.1 3646.9,1587.9 3664.69,1605.68 C25.1@3710.31,1605.68 ; U2.1@3692.6,1447.93 3739.85,1400.68 3780.68,1400.68 3825.56,1445.56 R23.2@3851,1445.56 R19.1@3851,1503.44 R20.1@3905.88,1503.44 ; R56.1@3907.44,1444 R20.1@3907.44,1505
NetC25_2: C25.2 C26.2 R16.1 U1.2 U2.2 | length 1150.9
  Bottom Layer w20: U1.2@3025,1650 3081,1650 3103,1628 3103,1601.56 3509.56,1601.56 3640,1732 3723,1732 3749.69,1705.31 C25.2@3749.69,1605.68 3786.31,1605.68 3807,1585 3807,1529 3778.72,1500.72 3767.4,1500.72 U2.2@3767.4,1447.93
NetC26_1: C26.1 R22.2 | length 75
  Bottom Layer w20: R22.2@3690,1558.24 C26.1@3765,1558.24
NetC27_1: C27.1 R24.2 U3.4 | length 124.2
  Bottom Layer w25: U3.4@5100.95,1394.12 C27.1@5100.95,1448.33 ; C27.1@5103.65,1451.03 R24.2@5173.65,1451.03
NetC29_1: C29.1 D7.1 U4.14 | length 299.2
  Bottom Layer w20: U4.14@1037,2836.3 1037,2923 1072.02,2958.02 C29.1@1235,2958.02
NetC34_1: C34.1 U5.3 | length 69.3
  Bottom Layer w25: U5.3@4600,3505.28 C34.1@4600,3574.56
NetC35_1: C35.1 R35.1 U5.7 | length 143.2
  Bottom Layer w25: U5.7@4550,3290.72 4550,3262 4570.44,3241.56 4570.44,3214 C35.1@4570.44,3156
NetC38_1: C38.1 R41.1 U7.4 | length 187.6
  Bottom Layer w12: R41.1@4840.39,1540.64 4858.07,1540.64 4867.54,1531.18 C38.1@4867.54,1460.33 U7.4@4867.54,1374.68
NetC38_2: C38.2 R42.1 U7.3 | length 197
  Bottom Layer w12: U7.3@4761.24,1368.78 C38.2@4761.24,1460.33 4761.24,1525.18 4776.7,1540.64 R42.1@4795.39,1540.64
NetC39_1: C39.1 D10.1 R39.1 | length 610.9
  Top Layer w50: D10.1@2354.28,239.72 C39.1@2735,239.72 R39.1@2965.19,239.72
NetC40_1: C40.1 C41.1 D8.2 D10.2 RT1.2 | length 1801
  Top Layer w50: C41.1@1545,89.21 1987.21,89.21 D10.2@2323.57,425.57
  Bottom Layer w50: RT1.2@695,167.36 892.64,167.36 970.79,89.21 C40.1@1130,89.21 C41.1@1545,89.21 ; D8.2@1979.49,89.21 D8.2@1980,89.72
NetC40_2: C40.2 C41.2 D9.2 D10.3 J3.1 N.1 RV1.1 | length 2693.6
  Top Layer w50: C41.2@1545,990.79 1968.21,990.79 1989,996 D10.3@2330,655
  Bottom Layer w25: J3.1@185,1300 N.1@185,1580
  Bottom Layer w50: J3.1@185,1300 RV1.1@613.31,1300 ; RV1.1@615.63,1302.32 818.46,1302.32 C40.2@1130,990.79 C41.2@1545,990.79
NetC42_2: C42.2 R44.1 R50.2 U6.3 | length 140.2
  Bottom Layer w20: R50.2@4480.39,1247.01 4481.39,1246.01 C42.2@4528.39,1246.01 ; R50.2@4481.39,1248.01 R44.1@4481.39,1290.64 U6.3@4530.54,1290.64
NetC43_1: C43.1 R48.1 R52.2 U6.1 | length 246.6
  Bottom Layer w20: R52.2@4571.07,1444.33 4571.07,1371.64 4605.79,1336.93 U6.1@4605.79,1290.2 ; C43.1@4606.39,1245.01 U6.1@4606.39,1289.6 ; U6.1@4607.92,1292.33 4641.39,1292.33
NetC46_1: C46.1 D6.1 R17.1 R18.2 | length 391
  Bottom Layer w20: C46.1@3472,1486.56 3472,1531.56 R18.2@3470.56,1533 3472.3,1534.74 D6.1@3574.52,1534.74 ; D6.1@3574.52,1533 D6.1@3574.52,1534.74 ; D6.1@3578,1534.74 3576.26,1534.74 D6.1@3574.52,1534.74 ; R17.1@3691.85,1675 3622.42,1675 3574.52,1627.1 D6.1@3574.52,1534.74
  Bottom Layer w25: C46.1@3470.56,1488 C46.1@3472,1486.56 ; D6.1@3574.52,1533 D6.1@3576.26,1534.74
NetC46_2: C46.2 R57.2 | length 59.4
  Bottom Layer w20: R57.2@3413,1430.46 3413.98,1431.44 C46.2@3472,1431.44
NetD1_2: D1.2 R3.1 | length 70.2
  Bottom Layer w25: D1.2@1588,3665.47 R3.1@1588,3735.63
NetD3_1: D3.1 R5.2 | length 88.1
  Bottom Layer w50: R5.2@1805.75,2348.5 D3.1@1893.83,2347.2
NetD3_2: D3.2 T1.6 | length 276.6
  Bottom Layer w50: D3.2@2021.78,2347.2 T1.6@2230.79,2528.31
NetD4_2: D4.2 R8.1 | length 206
  Bottom Layer w25: D4.2@1210,3085.53 1210,3114.57 1250.43,3155 1320,3155 1334,3169 R8.1@1334,3199.44
NetD7_2: D7.2 R25.2 | length 64.1
  Bottom Layer w25: R25.2@1031.56,3108 D7.2@1095.68,3108
NetD8_1: D8.1 D9.1 HV_diode.1 R26.1 | length 901.1
  Bottom Layer w25: D8.1@1971,488 D9.1@1971,588 2116,733 2116,1122.15 ; R26.1@2043.15,1195 2116,1122.15 ; HV_diode.1@2219.85,1122.15 2116,1122.15
NetD11_1: D11.1 R43.1 | length 92
  Bottom Layer w25: D11.1@1169.01,2189.8 D11.1@1169.96,2190.74 1170.43,2190.27 1259.79,2190.27 R43.1@1260.26,2189.8
NetHG_1: HG.1 Q1.1 R1.2 R3.2 R4.2 | length 1445.9
  Top Layer w25: HG.1@1117,4267 1128,4278 1341,4278 1533,4086 v1(1533,3810)
  Bottom Layer w25: R1.2@1477,3813.5 R3.2@1587.13,3813.5 ; R3.2@1588,3814.37 1622.63,3849 1899,3849 1951,3797 Q1.1@1951,3716.94 ; Q1.1@1976.65,3691.29 R4.2@2057.36,3691.29
NetHV_1: HV.1 R28.2 U4.1 | length 1999.4
  Top Layer w25: v3(1203,2583) 1317.27,2468.73 1317.27,2250.99 1492.5,2075.76 v1(1492.5,1285.5)
  Bottom Layer w25: U4.1@1137,2623.7 1162.3,2623.7 v3(1203,2583) ; HV.1@1261,1200 1357,1104 1509,1104 1536.85,1131.85 R28.2@1536.85,1195 1492.5,1239.35 v1(1492.5,1285.5)
NetI_opt_1: I_opt.1 R21.2 U1.3 | length 191
  Bottom Layer w20: I_opt.1@2534,1650 U1.3@2725,1650
NetJ3_3: J3.3 L.1 RT1.1 RV1.2 | length 1334.8
  Bottom Layer w25: L.1@180,610 180,895 J3.3@185,900
  Bottom Layer w50: J3.3@185,900 355,900 422.68,967.68 RV1.2@694.37,967.68 695,967.05 RT1.1@695,462.64
NetLG_1: LG.1 Q3.1 R6.2 R8.2 R11.2 | length 1490.7
  Top Layer w20: LG.1@929,4276 929,4069 772,3912 772,3400 890,3282 v1(965,3282)
  Bottom Layer w20: v1(965,3282) 1167,3282 1195.44,3253.56 R6.2@1261,3253.56
NetQ6_3: Q6.3 R56.2 | length 62.5
  Bottom Layer w20: R56.2@3962.56,1444 3963.56,1445 Q6.3@4024.69,1445
NetR16_2: R16.2 R18.1 R57.1 U1.1 | length 445.9
  Bottom Layer w20: U1.1@3025,1550 3160.17,1550 3177.17,1533 R18.1@3415.44,1533 3413,1530.56 R57.1@3413,1485.58
NetR26_2: R26.2 R27.1 | length 93.7
  Bottom Layer w25: R27.1@1843.15,1195 R26.2@1936.85,1195
NetR27_2: R27.2 R28.1 | length 93.7
  Bottom Layer w25: R28.1@1643.15,1195 R27.2@1736.85,1195
NetR29_1: R29.1 R30.2 | length 44.9
  Bottom Layer w25: R29.1@209.15,3171 R30.2@254,3171
NetR30_1: R30.1 R34.2 | length 31.5
  Bottom Layer w25: R30.1@376.99,3171 R34.2@408.46,3171.51
NetR31_2: R31.2 U5.1 | length 54.3
  Bottom Layer w25: R31.2@4445.72,3505.28 U5.1@4500,3505.28
NetR32_1: R32.1 U5.8 | length 570.5
  Top Layer w25: v3(4455,2950) 4455,3044.17 4437.56,3061.62 4411,3088.17 4411,3256 v1(4500,3345)
  Bottom Layer w25: R32.1@4434,3007.44 4437.56,3003.89 4455,2986.44 v3(4455,2950) ; U5.8@4500,3290.72 v1(4500,3345)
NetR39_2: R39.2 R40.1 | length 215
  Top Layer w50: R39.2@3087.09,232 R40.1@3087.09,447
NetR40_2: R40.2 R45.1 | length 190
  Top Layer w50: R40.2@2972.91,447 R45.1@2972.91,637
NetR45_2: R45.2 R49.1 | length 195
  Top Layer w50: R45.2@3087.09,637 R49.1@3087.09,832
NetR48_2: R48.2 U7.1 | length 65.4
  Bottom Layer w20: R48.2@4695.07,1292.33 4759.59,1292.33 U7.1@4760.19,1292.93
NetR53_2: R53.2 U5.6 | length 271.9
  Bottom Layer w12: R53.2@4405.56,3365 4405.56,3373.87 4575.13,3373.87 4600,3349 U5.6@4600,3290.72
NetR54_1: R54.1 U5.4 | length 449.5
  Bottom Layer w12: R54.1@4273.56,3417 4624,3417 4650,3443 U5.4@4650,3505.28
NetR55_1: R55.1 U5.5 | length 61.7
  Bottom Layer w20: U5.5@4650.72,3290 R55.1@4712.44,3290
OVP/OTP: C31.1 D11.2 OVP_OTP.1 R46.2 R47.2 U4.4 | length 1113.5
  Top Layer w20: v1(1045.32,2114.05) 1047.23,2112.14 1047.23,1653.52 1074.2,1626.56 OVP_OTP.1@1074.2,1536.5
  Bottom Layer w20: U4.4@987,2623.7 988.81,2621.89 988.81,2578.03 998.22,2568.62 v1(998.22,2565.91) 998.22,2563.21 1010.43,2551 1010.43,2539.1 ; 1011.2,2440.81 1011.2,2538.32 ; 1018.99,2433.01 1048.03,2403.97 C31.1@1049.02,2403.97 1047.94,2402.89 1047.94,2272.24 R46.2@1046.86,2271.16 1043.94,2268.25 v1@1043.94,2116
PGND: C7.2 C13.2 C15.2 C16.1 C17.2 C18.2 C20.2 C21.2 C22.2 C24.2 C30.2 C31.2 C32.2 C39.2 D10.4 J2.1 J2.2 Q3.3 R11.1 R21.1 R36.1 R37.1 R38.1 R46.1 R47.1 R49.2 R51.1 T1.7 TP8.1 TP9.1 U4.10 | length 3544.8
  Top Layer w50: D10.4@2347,847 2585,1085 2585,1415 ; D10.4@2363.72,830.28 C39.2@2735,830.28 ; C39.2@2732.28,832 R49.2@2972.91,832
  Top Layer w100: C7.2@907,3465.36 1009.64,3465.36 1120,3355 1120,3001.72 C17.2@1392.72,2729
  Bottom Layer w20: R11.1@1330,3360.56 1330,3401
  Bottom Layer w35: R38.1@719.66,2459.16 C21.2@719.66,2388.92 719.66,2319.11 724.82,2324.27 R36.1@790.75,2324.27 836.84,2324.27 856.14,2343.57 856.14,2387.71 C13.2@857.34,2388.92 ; C32.2@1109.82,2474.16 1109.82,2405.18 1111.02,2403.97 C31.2@1112.01,2403.97 ; R46.1@1125.6,2271.16 C31.2@1125.6,2391.37
  Bottom Layer w50: 591,3016 591,3169 653,3231 867,3231 910,3274 C7.2@910,3462.36
  other v1: 2535,1815 2580,1815 2630,1815 2680,1815 1214.17,1951.22 1160.02,1952.23 1160.02,2001.65 1214.17,2001.65 1160.02,2055.7 1214.17,2055.7 1161.16,2106.71 1212.42,2106.71 1168.82,2274.92 1214.17,2275.61 1170.43,2336.45 1215.32,2336.45 1169.01,2392.36 1214.17,2391.56 1168.82,2440.9 1214.17,2440.9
